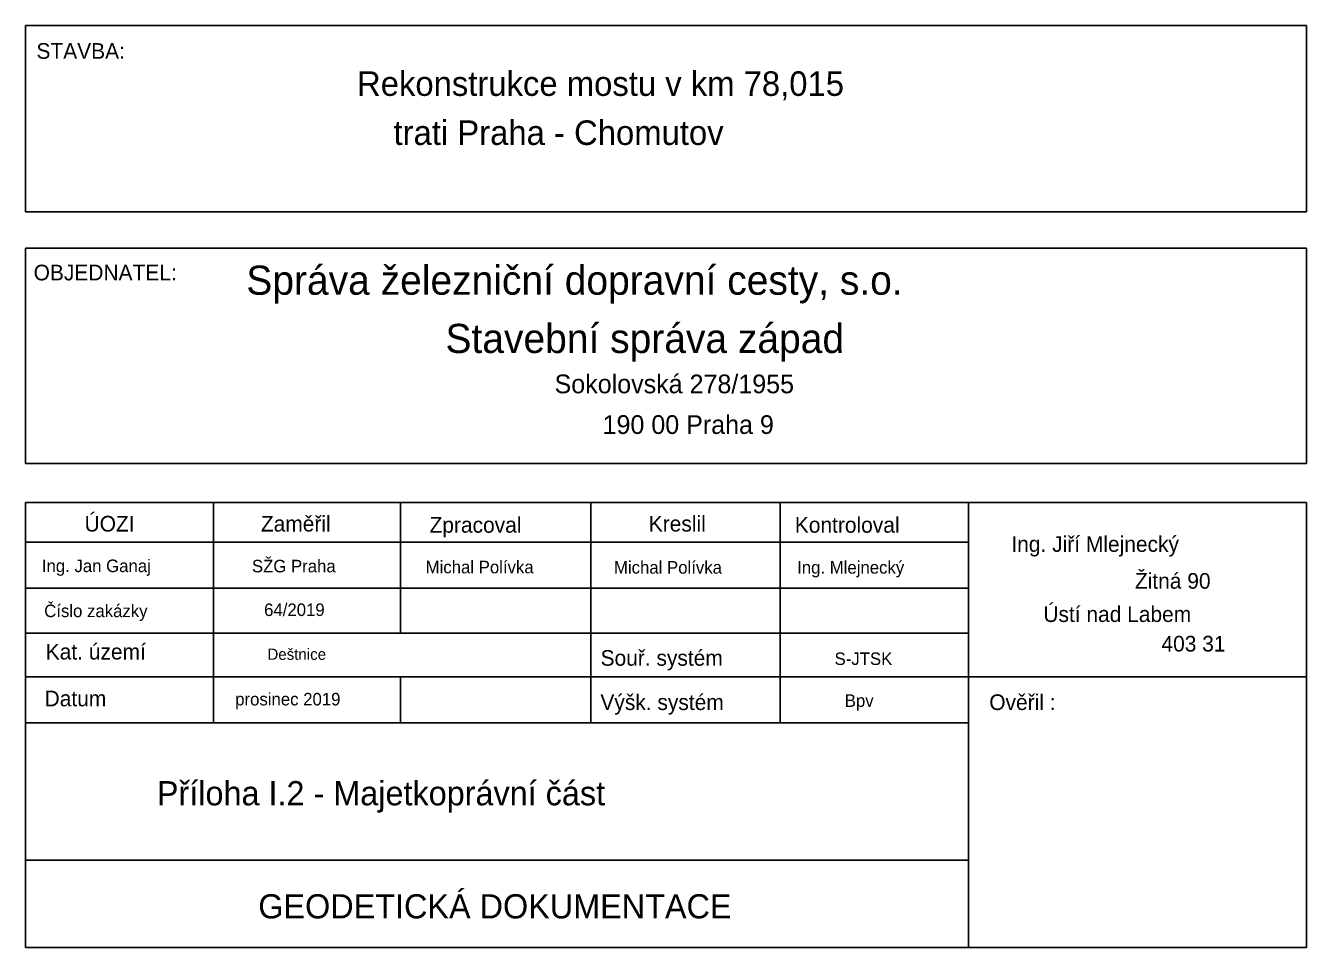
# Model space of a CAD drawing. Extents: x -879530 to -879371, y -1019242 to -1019127.
import ezdxf

# ---------------------------------------------------------------- set-up
doc = ezdxf.new("R2010")
doc.units = 0
doc.layers.add('LEGENDA', color=7, linetype='Continuous')
doc.layers.add('tabulka', color=7, linetype='Continuous')

msp = doc.modelspace()

# ---------------------------------------------------------------- linework, layer by layer
at = {"layer": 'tabulka'}
for p, q in [((-879530.09, -1019186.45), (-879371.44, -1019186.45)), ((-879506.8, -1019186.45), (-879506.8, -1019213.77)), ((-879483.66, -1019186.45), (-879483.66, -1019202.65)), ((-879460.06, -1019186.45), (-879460.06, -1019213.77)), ((-879436.61, -1019186.45), (-879436.61, -1019213.77)), ((-879413.31, -1019241.58), (-879413.31, -1019186.45)), ((-879530.09, -1019191.36), (-879413.31, -1019191.36)), ((-879530.09, -1019197.07), (-879413.31, -1019197.07)), ((-879530.09, -1019202.65), (-879413.31, -1019202.65)), ((-879530.09, -1019208.07), (-879371.44, -1019208.07)), ((-879483.66, -1019208.07), (-879483.66, -1019213.77)), ((-879530.09, -1019213.77), (-879413.31, -1019213.77)), ((-879530.09, -1019230.76), (-879413.31, -1019230.76))]:
    msp.add_line(p, q, dxfattribs=at)
for points in [[(-879530.09, -1019127.36), (-879371.44, -1019127.36), (-879371.44, -1019150.43), (-879530.09, -1019150.43)], [(-879530.09, -1019154.95), (-879371.44, -1019154.95), (-879371.44, -1019181.64), (-879530.09, -1019181.64)]]:
    msp.add_lwpolyline(points, close=True, dxfattribs=at)
msp.add_lwpolyline([(-879371.44, -1019186.45), (-879371.44, -1019241.58), (-879530.09, -1019241.58), (-879530.09, -1019186.45)], dxfattribs=at)

# ---------------------------------------------------------------- texts
at = {"layer": 'LEGENDA'}
for s, p in [('Rekonstrukce mostu v km 78,015 ', (-879489.04, -1019136.07)), ('    trati Praha - Chomutov', (-879489.04, -1019142.15))]:
    msp.add_text(s, height=3.04, dxfattribs=at).set_placement(p)
at = {"layer": 'tabulka'}
for s, height, p in [('STAVBA:', 1.94, (-879528.75, -1019131.47)), ('OBJEDNATEL:', 1.94, (-879529.1, -1019158.93)), ('Správa železniční dopravní cesty, s.o.', 3.61, (-879502.75, -1019160.71)), ('Stavební správa západ', 3.61, (-879478.08, -1019167.93)), ('Sokolovská 278/1955', 2.32, (-879464.57, -1019172.92)), ('190 00 Praha 9', 2.32, (-879458.62, -1019177.96)), ('ÚOZI', 1.94, (-879522.79, -1019190.05)), ('Zaměřil', 1.94, (-879500.95, -1019190.05)), ('Zpracoval', 1.94, (-879480.06, -1019190.2)), ('Kreslil', 1.94, (-879452.9, -1019190.05)), ('Kontroloval', 1.94, (-879434.81, -1019190.2)), ('Ing. Jiří Mlejnecký', 1.94, (-879407.98, -1019192.57)), ('Ing. Jan Ganaj', 1.552, (-879528.08, -1019195.08)), ('SŽG Praha', 1.552, (-879502.06, -1019195.11)), ('Michal Polívka', 1.552, (-879480.54, -1019195.23)), ('Michal Polívka', 1.552, (-879457.21, -1019195.27)), ('Ing. Mlejnecký', 1.552, (-879434.52, -1019195.27)), ('Žitná 90', 1.94, (-879392.68, -1019197.14)), ('Číslo zakázky', 1.552, (-879527.79, -1019200.66)), ('64/2019', 1.552, (-879500.55, -1019200.52)), ('Ústí nad Labem', 1.94, (-879404.02, -1019201.26)), ('403 31', 1.94, (-879389.39, -1019204.92)), ('Kat. území', 1.94, (-879527.6, -1019205.91)), ('Deštnice', 1.397, (-879500.14, -1019205.95)), ('Souř. systém', 1.94, (-879458.87, -1019206.68)), ('S-JTSK', 1.552, (-879429.88, -1019206.59)), ('Datum', 1.94, (-879527.74, -1019211.71)), ('prosinec 2019', 1.552, (-879504.13, -1019211.6)), ('Výšk. systém', 1.94, (-879458.89, -1019212.17)), ('Bpv', 1.552, (-879428.62, -1019211.78)), ('Ověřil :', 1.94, (-879410.72, -1019212.17)), ('Příloha I.2 - Majetkoprávní část', 3, (-879513.83, -1019223.98)), ('GEODETICKÁ DOKUMENTACE ', 3, (-879501.27, -1019237.99))]:
    msp.add_text(s, height=height, dxfattribs=at).set_placement(p)

doc.saveas('drawing.dxf')
